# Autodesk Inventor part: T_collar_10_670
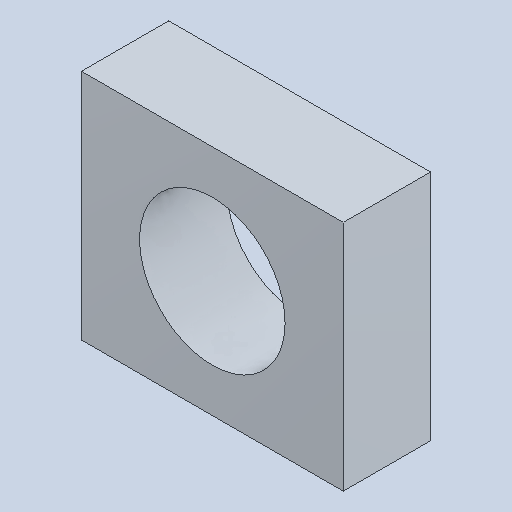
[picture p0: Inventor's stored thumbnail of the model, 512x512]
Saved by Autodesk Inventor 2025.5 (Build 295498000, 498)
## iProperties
Created: 2026-10
Part Number: T_collar_10_670
Material: Genérico
Document SubType Name: Modeling
Designer: Luis M
Density: 1 g/cm^3
Appearance: Valor por defecto
Author: Luis M
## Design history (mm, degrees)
feature "Base1"
node "Sólido1"
